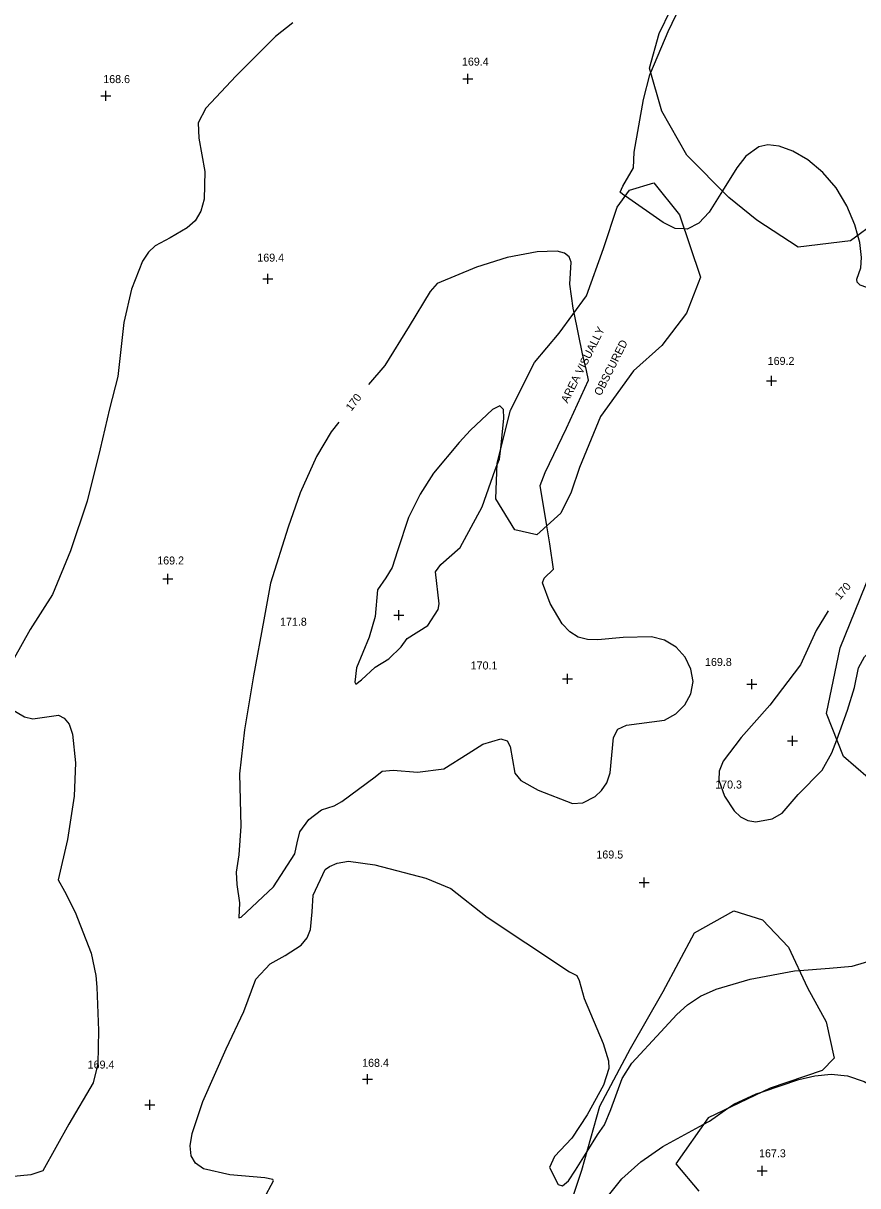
# Model space of a CAD drawing. Extents: x 1467615 to 2003689, y 770235 to 1108726.
# Drawn here: x 1998713.9 to 1998922.6, y 775623.3 to 775913.9 of the extents above; entities that cross this region are included whole.
import ezdxf

# ---------------------------------------------------------------- set-up
doc = ezdxf.new("R2010")
doc.units = 0
for name, color, linetype in [('RD_DTM_Major1', 7, 'Continuous'), ('RD_DTM_Major1_Lbl', 7, 'Continuous'), ('RD_DTM_Major2', 7, 'Continuous'), ('RD_DTM_Minor1', 7, 'Continuous'), ('RD_DTM_Minor2', 7, 'Continuous'), ('RD_DTM_Obscure', 7, 'Continuous'), ('RD_DTM_Spot_Elev', 7, 'Continuous'), ('RD_TX_Misc1', 7, 'Continuous')]:
    doc.layers.add(name, color=color, linetype=linetype)

msp = doc.modelspace()

# ---------------------------------------------------------------- linework, layer by layer
at = {"layer": 'RD_DTM_Major1'}
for points in [[(1998851.64, 775841.53), (1998851.4, 775842.72), (1998850.59, 775848.67), (1998850.92, 775854.21), (1998850.41, 775855.51), (1998849.29, 775856.48), (1998847.45, 775856.97), (1998842.41, 775856.82), (1998834.89, 775855.36), (1998827.29, 775852.94), (1998817.38, 775848.89), (1998815.65, 775846.9), (1998810.41, 775838.21), (1998804.28, 775828.4), (1998800.26, 775823.63)], [(1998792.78, 775814.24), (1998790.93, 775811.78), (1998787.22, 775805.58), (1998783.12, 775796.52), (1998780.12, 775787.98), (1998775.72, 775773.97), (1998774.07, 775764.76), (1998771.5, 775750.81), (1998769.22, 775737.28), (1998767.96, 775726.29), (1998768.33, 775713.25), (1998767.79, 775706.05), (1998767.12, 775701.7), (1998767.3, 775698.67), (1998767.92, 775694.03), (1998767.77, 775690.3), (1998768.39, 775690.45), (1998776.44, 775698.06), (1998781.82, 775706.34), (1998782.35, 775709.03), (1998783.04, 775711.77), (1998785.29, 775714.87), (1998788.49, 775717.31), (1998791.67, 775718.32), (1998793.54, 775719.38), (1998801.92, 775725.55), (1998803.68, 775726.98), (1998806.39, 775727.23), (1998812.51, 775726.69), (1998819.07, 775727.57), (1998825.18, 775731.38), (1998828.82, 775733.73), (1998833.31, 775735.01), (1998834.89, 775734.58), (1998835.66, 775733.16), (1998836.86, 775726.45), (1998838.34, 775724.65), (1998842.67, 775722.21), (1998851.28, 775718.87), (1998853.82, 775719.07), (1998856.91, 775720.65), (1998858.5, 775722.1), (1998859.84, 775724.04), (1998860.72, 775726.52), (1998861.54, 775735.38), (1998862.64, 775737.43), (1998864.78, 775738.45), (1998874.28, 775739.75), (1998877.15, 775741.27), (1998879.4, 775743.52), (1998880.88, 775746.28), (1998881.41, 775749.35), (1998880.88, 775752.49), (1998879.41, 775755.44), (1998877.17, 775757.93), (1998874.31, 775759.68), (1998871.02, 775760.53), (1998863.96, 775760.39), (1998857.64, 775759.76), (1998855.01, 775759.86), (1998852.67, 775760.47), (1998850.58, 775761.77), (1998848.69, 775763.83), (1998845.71, 775768.85), (1998843.77, 775774.05), (1998844.2, 775775.19), (1998846.47, 775777.48), (1998845.56, 775783.77), (1998844.82, 775788.31)], [(1998915.19, 775767.05), (1998912.18, 775762.11), (1998908.31, 775753.56), (1998900.63, 775743.44), (1998893.44, 775735.42), (1998888.96, 775729.47), (1998887.99, 775726.93), (1998887.88, 775724.7), (1998889.29, 775720.72), (1998891.73, 775717.03), (1998893.29, 775715.59), (1998895.1, 775714.65), (1998897.16, 775714.34), (1998901.21, 775715.07), (1998903.7, 775716.5), (1998907.73, 775721.16), (1998913.75, 775727.19), (1998916.17, 775731.57), (1998917.37, 775734.83)]]:
    msp.add_lwpolyline(points, dxfattribs=at)
at = {"layer": 'RD_DTM_Major2'}
for points in [[(1998844.82, 775788.31), (1998843.18, 775798.38), (1998844.45, 775801.66), (1998849.74, 775812.74), (1998855.24, 775824.67), (1998854.77, 775827.11), (1998853.73, 775831.29), (1998851.64, 775841.53)], [(1998917.37, 775734.83), (1998920.09, 775742.2), (1998921.8, 775747.84), (1998922.83, 775752.83), (1998924.34, 775755.56), (1998927.39, 775758.82), (1998932.36, 775762.76), (1998944.72, 775770.97), (1998949.99, 775774.2), (1998957.51, 775779), (1998956.86, 775779.68), (1998955.29, 775781.22), (1998953.52, 775782.95), (1998950.16, 775784.52), (1998945.02, 775785.45), (1998938.64, 775785.45), (1998935.13, 775784.82), (1998931.44, 775783.46), (1998927.68, 775781.18)]]:
    msp.add_lwpolyline(points, dxfattribs=at)
at = {"layer": 'RD_DTM_Minor1'}
for points in [[(1998781.34, 775914.03), (1998776.95, 775910.59), (1998767.09, 775900.79), (1998759.52, 775892.69), (1998757.59, 775889.03), (1998757.8, 775885.2), (1998759.3, 775876.86), (1998759.14, 775869.93), (1998758.3, 775866.91), (1998756.83, 775864.54), (1998754.91, 775862.74), (1998750.62, 775860.3), (1998746.86, 775858.24), (1998745.22, 775856.7), (1998743.69, 775854.44), (1998740.96, 775847.43), (1998739.04, 775839.12), (1998737.54, 775825.62), (1998735.44, 775817.51), (1998733.08, 775807.55), (1998729.87, 775794.49), (1998725.66, 775782.06), (1998721.18, 775771.1), (1998715.62, 775762.38), (1998711.57, 775755.22)], [(1998864.49, 775870.73), (1998863.88, 775871.15), (1998863.2, 775871.72), (1998863.83, 775873.17), (1998866.49, 775877.76), (1998866.65, 775881.72), (1998869.02, 775894.83), (1998870.6, 775901), (1998870.85, 775901.6)], [(1998888.8, 775872), (1998885.49, 775866.7), (1998882.84, 775863.95), (1998879.96, 775862.45), (1998879.21, 775862.5)], [(1998951.52, 775832.61), (1998951.47, 775834.09), (1998951.45, 775847.08), (1998951.16, 775850.6), (1998950.27, 775853.18), (1998948.44, 775854.49), (1998945.51, 775854.34), (1998941.9, 775853.11), (1998929.31, 775847.13), (1998926.28, 775847.37), (1998923.24, 775848.49), (1998922.45, 775849.2), (1998922.42, 775849.98), (1998923.4, 775852.76), (1998923.6, 775855.38), (1998923.11, 775859.09), (1998922.62, 775860.87)], [(1998833.32, 775807.62), (1998834.12, 775815.17), (1998833.97, 775817.35), (1998833.07, 775818.26), (1998831.21, 775817.41), (1998825.77, 775812.22), (1998822.94, 775809.11), (1998816.49, 775801.45), (1998813.14, 775796.23), (1998810.26, 775790.35), (1998807.49, 775782.08), (1998806.14, 775777.9), (1998804.54, 775775.25), (1998802.46, 775772.29), (1998801.88, 775765.62), (1998800.37, 775760.45), (1998797.26, 775752.83), (1998796.81, 775749.17), (1998797.05, 775748.7), (1998798.48, 775749.77), (1998801.93, 775752.96), (1998805.3, 775755.07), (1998808.43, 775758.05), (1998809.93, 775760.15), (1998815.04, 775763.4), (1998817.69, 775767.34), (1998817.89, 775768.76), (1998816.96, 775776.81), (1998818.33, 775778.59), (1998823.17, 775782.84), (1998828.7, 775793.08), (1998831.93, 775802.3), (1998832.36, 775803.35)], [(1998908.01, 775677.12), (1998915.56, 775677.74), (1998921.22, 775678.26), (1998927.37, 775680.05), (1998937.53, 775684.42), (1998947.54, 775687.49), (1998955.39, 775689.25), (1998960.5, 775689.02), (1998970.47, 775686.92), (1998974.02, 775687.33), (1998977.43, 775688.95), (1998980.61, 775691.58), (1998983.46, 775694.87), (1998987.81, 775702.16), (1998990.67, 775709.57), (1998994.24, 775721.16), (1998996, 775728.54), (1998996.62, 775734.8), (1998997.09, 775743.41), (1998999.18, 775747.97), (1999004.15, 775755.62)], [(1998710.51, 775742.72), (1998714.17, 775740.57), (1998716.25, 775740.04), (1998722.71, 775740.97), (1998724.12, 775740.24), (1998725.31, 775738.7), (1998726.16, 775736.2), (1998726.9, 775729.04), (1998726.58, 775720.71), (1998724.97, 775709.87), (1998722.6, 775699.78), (1998724.16, 775697), (1998726.85, 775691.73), (1998730.86, 775681.43), (1998732.05, 775675.85), (1998732.29, 775672.97), (1998732.68, 775662.16), (1998732.51, 775653.81), (1998731.35, 775649.05), (1998725.24, 775638.72), (1998718.73, 775627.03), (1998715.75, 775626.08), (1998706.24, 775625.13)], [(1998774.06, 775620.06), (1998776.49, 775624.53), (1998776.3, 775624.89), (1998774.34, 775625.28), (1998765.55, 775626.03), (1998758.98, 775627.59), (1998756.92, 775628.96), (1998755.83, 775630.83), (1998755.59, 775633.28), (1998756.1, 775636.41), (1998758.76, 775644.36), (1998764.63, 775657.56), (1998769.01, 775666.89), (1998772.04, 775674.94), (1998775.61, 775678.79), (1998779.39, 775680.9), (1998783.35, 775683.49), (1998784.88, 775685.27), (1998785.74, 775687.38), (1998786.11, 775691.81), (1998786.41, 775695.96), (1998789.37, 775702.41), (1998790.51, 775703.16), (1998792.4, 775703.97), (1998795.25, 775704.46), (1998801.78, 775703.57), (1998814.57, 775700.21), (1998820.84, 775697.62), (1998829.89, 775690.5), (1998839.61, 775684.03), (1998850.51, 775676.81), (1998852.38, 775675.91), (1998852.94, 775674.63), (1998854.19, 775670.1), (1998858.9, 775658.85), (1998860.26, 775654.56), (1998860.33, 775652.68), (1998859.05, 775648.44), (1998854.94, 775641.06), (1998851.1, 775635.2), (1998846.76, 775630.65), (1998845.52, 775627.89), (1998847.68, 775623.63), (1998848.79, 775623.31), (1998850.29, 775624.52), (1998852, 775627.2), (1998854.93, 775631.92)], [(1998898.78, 775646.82), (1998907.87, 775649.86), (1998911.86, 775650.81), (1998915.96, 775651.23), (1998920.09, 775650.82), (1998924.21, 775649.37), (1998928.36, 775647), (1998934.24, 775642.45)], [(1998883.97, 775638.61), (1998885.53, 775639.46), (1998890.16, 775642.72)]]:
    msp.add_lwpolyline(points, dxfattribs=at)
at = {"layer": 'RD_DTM_Minor2'}
for points in [[(1998870.85, 775901.6), (1998875.18, 775911.85), (1998879.32, 775920.48), (1998882.46, 775925.06), (1998885.06, 775926.84), (1998889.58, 775928.44), (1998900.61, 775931.17), (1998905.2, 775935.03), (1998912.52, 775941.35), (1998914.45, 775943.66), (1998915.61, 775945.89), (1998916.4, 775949.79), (1998916.89, 775952.36), (1998917.38, 775953.46)], [(1998922.62, 775860.87), (1998921.89, 775863.55), (1998919.92, 775868.27), (1998917.23, 775872.78), (1998913.87, 775876.65), (1998910.14, 775879.74), (1998906.38, 775881.96), (1998902.95, 775883.23), (1998900.11, 775883.52), (1998897.85, 775883.03), (1998894.64, 775880.73), (1998892.41, 775877.78), (1998888.8, 775872)], [(1998879.21, 775862.5), (1998876.94, 775862.65), (1998873.98, 775864.1), (1998864.49, 775870.73)], [(1998832.36, 775803.35), (1998833.04, 775804.98), (1998833.32, 775807.62)], [(1998854.93, 775631.92), (1998857.5, 775636.07), (1998859.26, 775638.57), (1998860.85, 775642.4), (1998863.65, 775650.11), (1998866.1, 775653.96), (1998873.36, 775661.8), (1998877.33, 775666.18), (1998880.04, 775668.53), (1998883.32, 775670.69), (1998887.18, 775672.47), (1998895.71, 775674.99), (1998906.83, 775677.02), (1998908.01, 775677.12)], [(1998890.16, 775642.72), (1998891.64, 775643.76), (1998897.19, 775646.29), (1998898.78, 775646.82)], [(1998844.29, 775599.25), (1998848.3, 775604.11), (1998854.3, 775611.56), (1998860.57, 775621.3), (1998863.62, 775625.04), (1998868.32, 775629.27), (1998873.82, 775633.13), (1998883.97, 775638.61)]]:
    msp.add_lwpolyline(points, dxfattribs=at)
at = {"layer": 'RD_DTM_Obscure'}
for points in [[(1998933.98, 775869.18), (1998920.82, 775859.56), (1998907.72, 775857.97), (1998897.37, 775864.66), (1998890.41, 775870.39), (1998879.89, 775880.92), (1998873.6, 775891.97), (1998870.55, 775902.67), (1998872.93, 775911.34), (1998878.75, 775923.44)], [(1998871.58, 775874), (1998878.03, 775866), (1998883.3, 775850.41), (1998879.75, 775841.42), (1998873.57, 775833.33), (1998866.53, 775827.02), (1998858.26, 775815.61), (1998852.98, 775802.88), (1998850.92, 775796.68), (1998848.34, 775791.47), (1998842.31, 775786.06), (1998836.83, 775787.31), (1998832.09, 775795.02), (1998832.39, 775803.99), (1998835.78, 775817.18), (1998841.78, 775829.09), (1998847.92, 775836.41), (1998854.74, 775845.79), (1998859.02, 775857.61), (1998862.45, 775867.94), (1998865.55, 775872.17), (1998871.58, 775874)], [(1998925.23, 775725.3), (1998919.02, 775730.61), (1998914.83, 775741.35), (1998918.21, 775757.8), (1998928.36, 775782.86)], [(1998847.23, 775608.11), (1998853.61, 775627.22), (1998858.1, 775643.19), (1998865.76, 775657.66), (1998873.97, 775671.89), (1998881.82, 775686.53), (1998891.65, 775692.09), (1998898.77, 775689.8), (1998905.27, 775682.96), (1998910.05, 775672.78), (1998914.74, 775664.32), (1998916.73, 775655.25), (1998913.7, 775652.17), (1998900.67, 775647.72), (1998885.18, 775640.35), (1998877.11, 775628.77), (1998882.85, 775621.97)]]:
    msp.add_lwpolyline(points, dxfattribs=at)
at = {"layer": 'RD_DTM_Spot_Elev'}
for p, q in [((1998825.05, 775898.8), (1998825.05, 775901.3)), ((1998823.8, 775900.05), (1998826.3, 775900.05)), ((1998733.24, 775895.8), (1998735.74, 775895.8)), ((1998734.49, 775894.55), (1998734.49, 775897.05)), ((1998773.8, 775850.05), (1998776.3, 775850.05)), ((1998775.05, 775848.8), (1998775.05, 775851.3)), ((1998901.03, 775823.31), (1998901.03, 775825.81)), ((1998899.78, 775824.56), (1998902.28, 775824.56)), ((1998750, 775773.75), (1998750, 775776.25)), ((1998748.75, 775775), (1998751.25, 775775)), ((1998807.78, 775764.69), (1998807.78, 775767.19)), ((1998806.53, 775765.94), (1998809.03, 775765.94)), ((1998848.8, 775750.05), (1998851.3, 775750.05)), ((1998850.05, 775748.8), (1998850.05, 775751.3)), ((1998896.1, 775747.43), (1998896.1, 775749.93)), ((1998894.85, 775748.68), (1998897.35, 775748.68)), ((1998906.29, 775733.26), (1998906.29, 775735.76)), ((1998905.04, 775734.51), (1998907.54, 775734.51)), ((1998869.22, 775697.92), (1998869.22, 775700.42)), ((1998867.97, 775699.17), (1998870.47, 775699.17)), ((1998800, 775648.75), (1998800, 775651.25)), ((1998798.75, 775650), (1998801.25, 775650)), ((1998744.31, 775643.56), (1998746.81, 775643.56)), ((1998745.56, 775642.31), (1998745.56, 775644.81)), ((1998898.71, 775625.81), (1998898.71, 775628.31)), ((1998897.46, 775627.06), (1998899.96, 775627.06))]:
    msp.add_line(p, q, dxfattribs=at)

# ---------------------------------------------------------------- texts
at = {"layer": 'RD_DTM_Major1_Lbl'}
for rotation, p in [(53.1386, (1998795.95, 775816.8)), (49.7563, (1998918.19, 775769.68))]:
    msp.add_text('170', height=2, rotation=rotation, dxfattribs=at).set_placement(p)
at = {"layer": 'RD_DTM_Spot_Elev'}
for s, p in [('169.4', (1998823.61, 775903.33)), ('168.6', (1998733.88, 775898.96)), ('169.4', (1998772.42, 775854.33)), ('169.2', (1998900.09, 775828.51)), ('169.2', (1998747.38, 775778.63)), ('171.8', (1998778.1, 775763.32)), ('170.1', (1998825.79, 775752.38)), ('169.8', (1998884.41, 775753.26)), ('170.3', (1998886.96, 775722.63)), ('169.5', (1998857.24, 775705.13)), ('169.4', (1998729.98, 775652.62)), ('168.4', (1998798.64, 775653.06)), ('167.3', (1998897.93, 775630.44))]:
    msp.add_text(s, height=2, dxfattribs=at).set_placement(p)
at = {"layer": 'RD_TX_Misc1'}
for s, p in [('AREA VISUALLY', (1998850.03, 775818.82)), ('OBSCURED', (1998858.33, 775820.61))]:
    msp.add_text(s, height=2, rotation=63.271, dxfattribs=at).set_placement(p)

doc.saveas('drawing.dxf')
